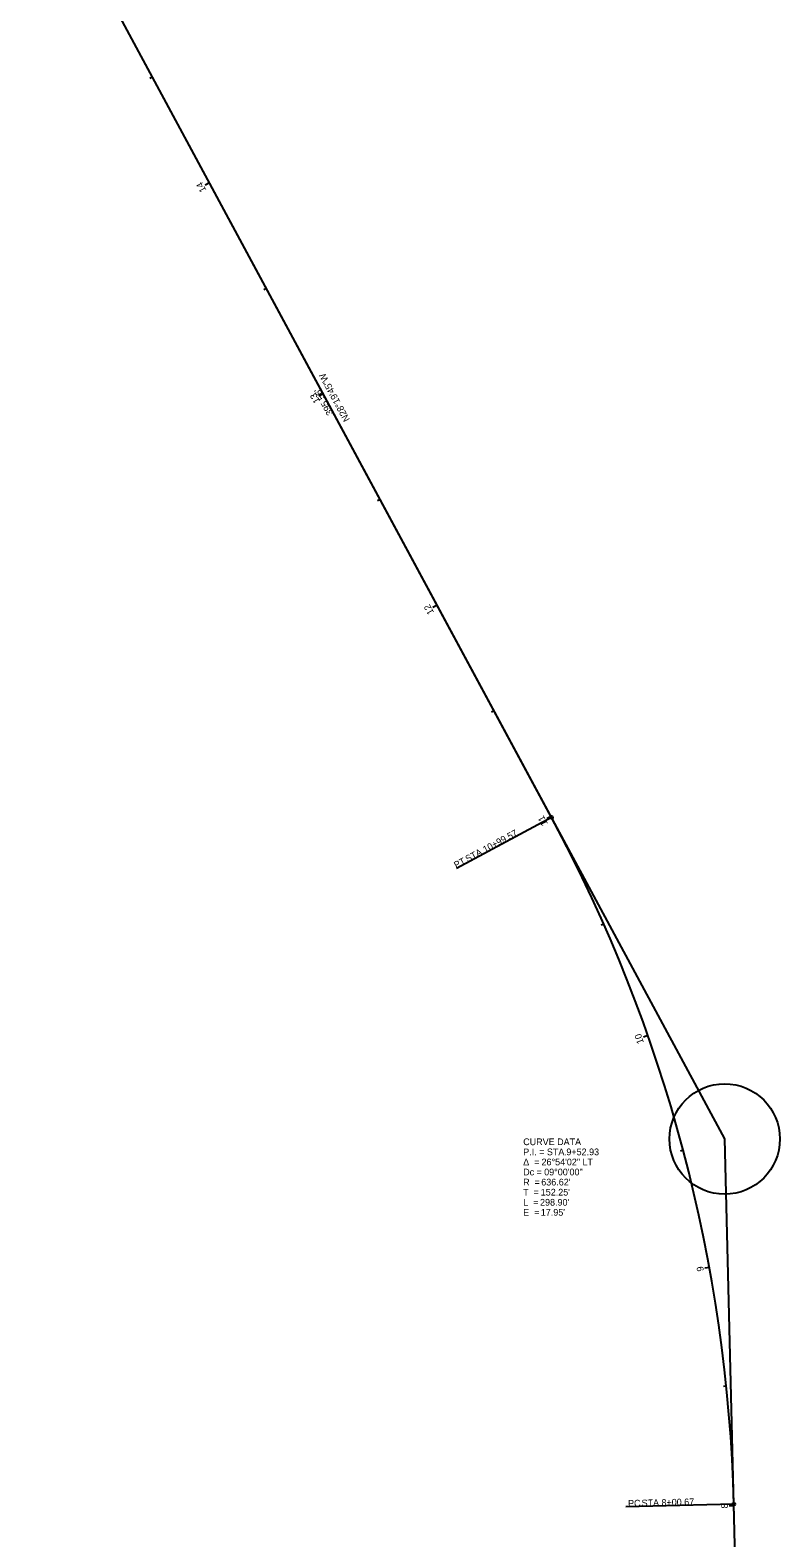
# Model space of a CAD drawing. Extents: x 140402 to 140969, y 345095 to 350073.
# Drawn here: x 140431 to 140744, y 345707 to 346336 of the extents above; entities that cross this region are included whole.
import ezdxf

# ---------------------------------------------------------------- set-up
doc = ezdxf.new("R2010")
doc.units = 0
for name, color, linetype in [('_CIVIL_CONSTRUCTION', 7, 'Continuous'), ('DR_X_Cells', 7, 'Continuous'), ('SC_Scratch1', 7, 'Continuous'), ('SN_X_Public', 7, 'Continuous'), ('SV_X_Control_Cells_Found', 7, 'Continuous'), ('SV_X_Mon_Cells_Found', 7, 'Continuous'), ('SV_X_Shot_Marker', 7, 'Continuous')]:
    doc.layers.add(name, color=color, linetype=linetype)

msp = doc.modelspace()

# ---------------------------------------------------------------- linework, layer by layer
at = {"layer": 'SC_Scratch1'}
for p, q in [((140648.71, 346007.71), (140609.1, 345986.36)), ((140724.76, 345721.48), (140679.77, 345720.36))]:
    msp.add_line(p, q, dxfattribs=at)
for centre in [(140648.71, 346007.71), (140724.76, 345721.48)]:
    msp.add_circle(centre, 0.6, dxfattribs=at)
at = {"layer": 'SN_X_Public'}
for p, q in [((140482.42, 346316.17), (140481.36, 346315.61)), ((140506.15, 346272.16), (140504.39, 346271.21)), ((140529.87, 346228.15), (140528.82, 346227.58)), ((140553.6, 346184.14), (140551.84, 346183.19)), ((140577.33, 346140.13), (140576.27, 346139.56)), ((140601.05, 346096.12), (140599.29, 346095.17)), ((140624.78, 346052.1), (140623.72, 346051.53)), ((140648.51, 346008.09), (140646.75, 346007.14)), ((140670.51, 345963.21), (140669.41, 345962.72)), ((140688.93, 345916.74), (140687.04, 345916.07)), ((140703.64, 345868.96), (140702.48, 345868.66)), ((140714.56, 345820.18), (140712.59, 345819.82)), ((140721.62, 345770.7), (140720.43, 345770.58)), ((140724.77, 345720.81), (140722.77, 345720.76))]:
    msp.add_line(p, q, dxfattribs=at)
at = {"layer": 'SV_X_Control_Cells_Found'}
for p, q in [((140720.96, 345873.69), (140431.46, 346410.7)), ((140739.38, 345135.1), (140720.96, 345873.69))]:
    msp.add_line(p, q, dxfattribs=at)
msp.add_circle((140720.93, 345873.67), 22.99, dxfattribs=at)
msp.add_arc((140088.33, 345705.61), 636.62, 1.42845, 28.32904, dxfattribs=at)
at = {"layer": 'SV_X_Mon_Cells_Found'}
for p, q in [((140648.71, 346007.71), (140461, 346355.9)), ((140739.38, 345135.1), (140724.76, 345721.48))]:
    msp.add_line(p, q, dxfattribs=at)
msp.add_arc((140088.33, 345705.61), 636.62, 1.42845, 28.32904, dxfattribs=at)

# ---------------------------------------------------------------- texts
at = {"layer": '_CIVIL_CONSTRUCTION'}
msp.add_text('N28°19\'45"W', height=2.8, rotation=118.32904, dxfattribs=at).set_placement((140564.79, 346173.5))
at = {"layer": 'DR_X_Cells'}
msp.add_text("395.56'", height=2.8, rotation=118.32904, dxfattribs=at).set_placement((140557.88, 346176.12))
at = {"layer": 'SC_Scratch1'}
for s, rotation, p in [('10+99.57', 28.32904, (140621.06, 345992.85)), (' STA. ', 28.32904, (140612.85, 345988.42)), ('PT', 28.32904, (140609.02, 345986.36)), ('PC', 1.42845, (140680.69, 345720.42)), (' STA. ', 1.42845, (140685.29, 345720.54)), ('8+00.67', 1.42845, (140694.61, 345720.77))]:
    msp.add_text(s, height=2.8, rotation=rotation, dxfattribs=at).set_placement(p)
at = {"layer": 'SN_X_Public'}
for s, rotation, p in [('14', 118.32904, (140504.97, 346269.07)), ('13', 118.32904, (140552.39, 346181.12)), ('12', 118.32904, (140599.85, 346093.09)), ('11', 118.32904, (140647.31, 346005.05)), ('10', 109.36782, (140687.28, 345913.88)), ('9', 100.36782, (140712.28, 345818.76)), ('8', 91.42845, (140722.3, 345719.73))]:
    msp.add_text(s, height=2.8, rotation=rotation, dxfattribs=at).set_placement(p)
at = {"layer": 'SV_X_Shot_Marker'}
for s, p in [('CURVE DATA', (140636.95, 345871.1)), ('P.I. = STA. ', (140636.95, 345866.9)), ('9+52.93', (140654.94, 345866.9)), ('Δ  = ', (140636.95, 345862.7)), ('Dc = ', (140636.95, 345858.5)), ('26°54\'02" LT', (140644.59, 345862.7)), ('09°00\'00"', (140645.69, 345858.5)), ('R  = ', (140636.95, 345854.3)), ("636.62'", (140644.48, 345854.3)), ('T  = ', (140636.95, 345850.1)), ('L  = ', (140636.95, 345845.9)), ("298.90'", (140643.98, 345845.9)), ("152.25'", (140644.27, 345850.1)), ('E  = ', (140636.95, 345841.7)), ("17.95'", (140644.29, 345841.7))]:
    msp.add_text(s, height=2.8, dxfattribs=at).set_placement(p)

doc.saveas('drawing.dxf')
